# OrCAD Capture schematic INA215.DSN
size B; title: LM20145/LM20145Q 5A, POWERWISE® ADJUSTABLE; rev: 1.1; note: Datasheet :SBOS437G
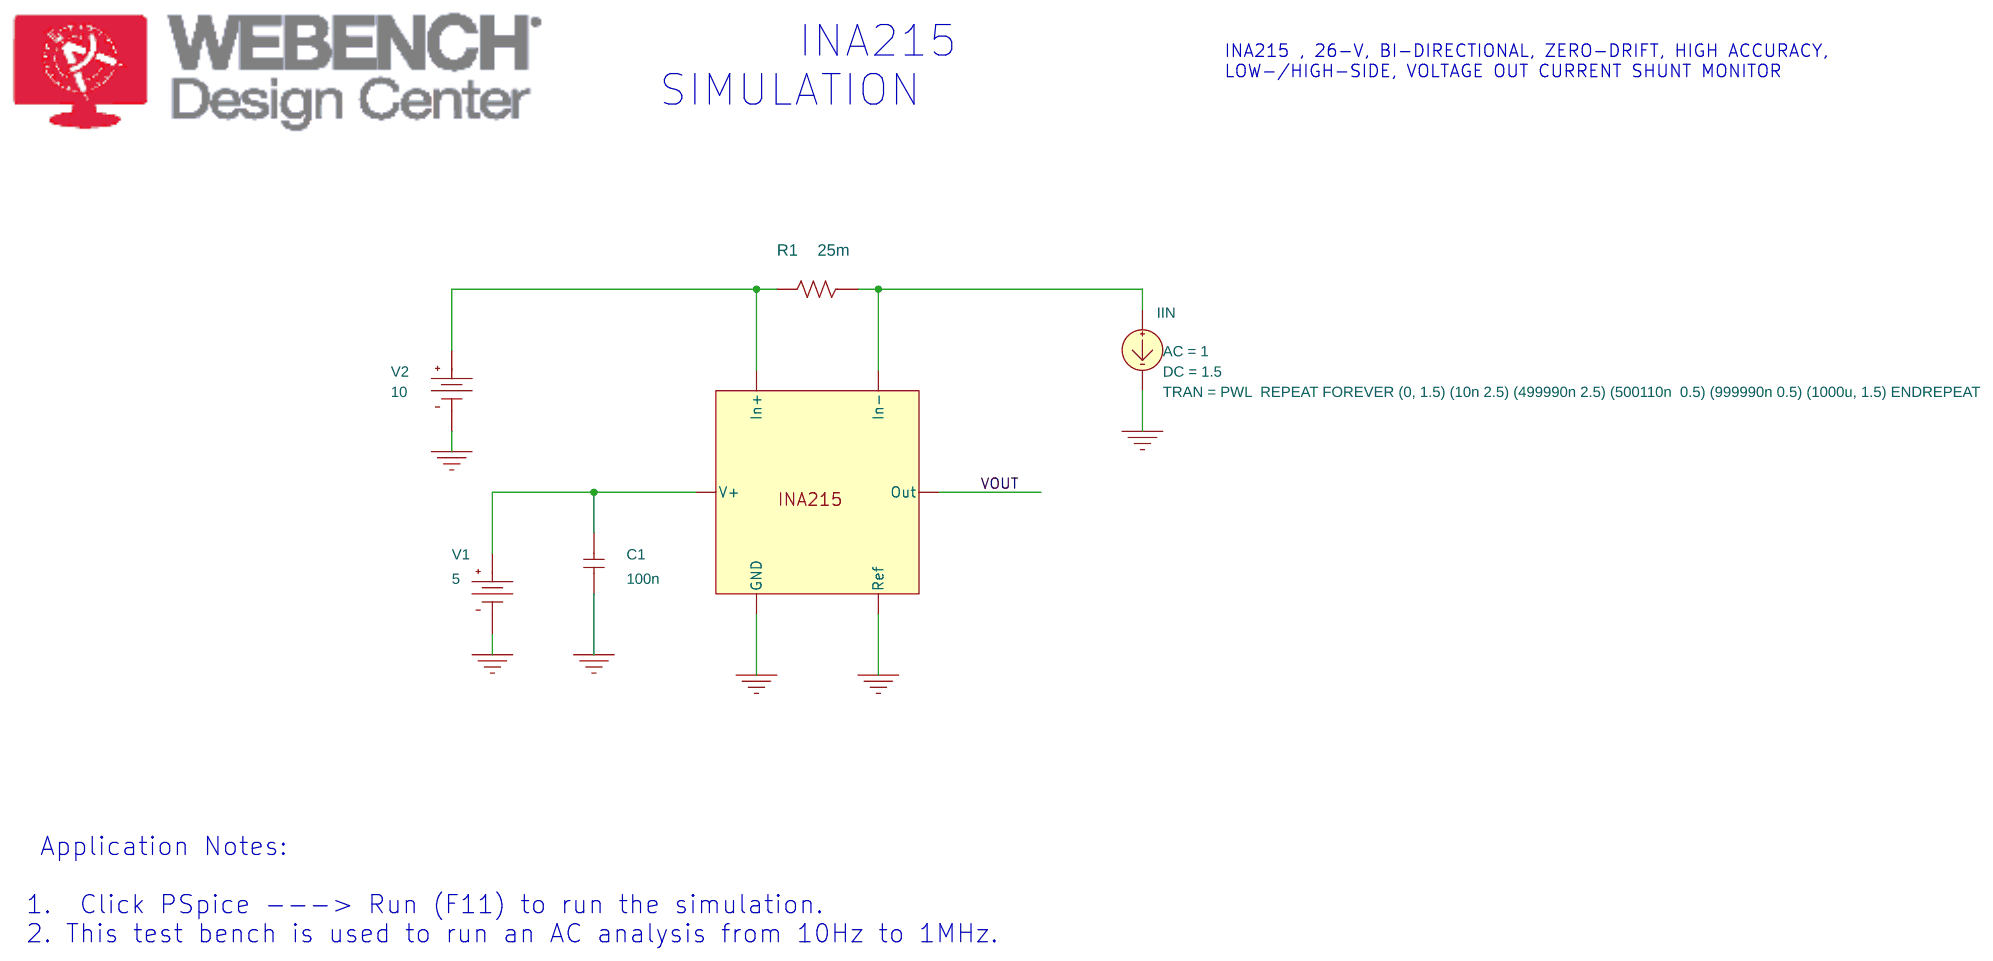
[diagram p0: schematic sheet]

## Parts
C1  100n  [RAD/CK05]
IIN  ISRC
R1  25m  [AX/RC05]
U1  INA215
V1  VDC
V2  VDC

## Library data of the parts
C1 = C
IIN = ISRC: AC: 1; DC: 1.5; TRAN: PWL  REPEAT FOREVER (0, 1.5) (10n 2.5) (499990n 2.5) (500110n  0.5) (999990n 0.5) (1000u, 1.5) ENDREPEAT
R1 = R
U1 = INA215
V1 = VDC: DC: 5
V2 = VDC: DC: 10

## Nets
0: C1.1 IIN.2(-) U1.GND U1.Ref V1.1(-) V2.1(-)
VOUT: U1.Out
N14305351: R1.2 U1.In+ V2.0(+)
N14305355: IIN.1(+) R1.1 U1.In-
N14305359: C1.2 U1.V+ V1.0(+)

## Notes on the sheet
- INA215
   SIMULATION
- INA215 , 26-V, BI-DIRECTIONAL, ZERO-DRIFT, HIGH ACCURACY,
- LOW-/HIGH-SIDE, VOLTAGE OUT CURRENT SHUNT MONITOR
- Application Notes:
  1.  Click PSpice ---> Run (F11) to run the simulation.
  2. This test bench is used to run an AC analysis from 10Hz to 1MHz.
